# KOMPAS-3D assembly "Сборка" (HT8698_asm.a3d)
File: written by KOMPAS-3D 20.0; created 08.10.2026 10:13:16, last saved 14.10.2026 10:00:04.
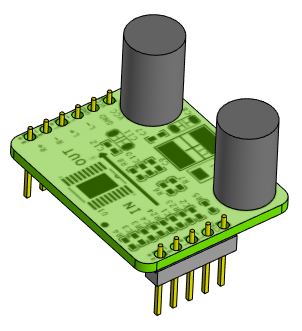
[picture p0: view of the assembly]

Document properties: Полное имя файла: D:\RicWork\Project-EPS32\box_compas\усилитель\HT8698_asm.a3d

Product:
- Part/product: Сборка
    Масса: 0.0191261
  - Component [detail]: Деталь  | Масса: 0.000651758; source file: ..\разъемы\pls_5.m3d
  - Component [detail]: Деталь  | Масса: 0.00078211; source file: ..\разъемы\pls_6.m3d
  - Component [detail]: Деталь  | Масса: 0.0176922; source file: HT8698.m3d

Referenced files in D:\RicWork\Project-EPS32\box_compas\усилитель\: HT8698.m3d
Referenced files in D:\RicWork\Project-EPS32\box_compas\разъемы\: pls_6.m3d, pls_5.m3d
